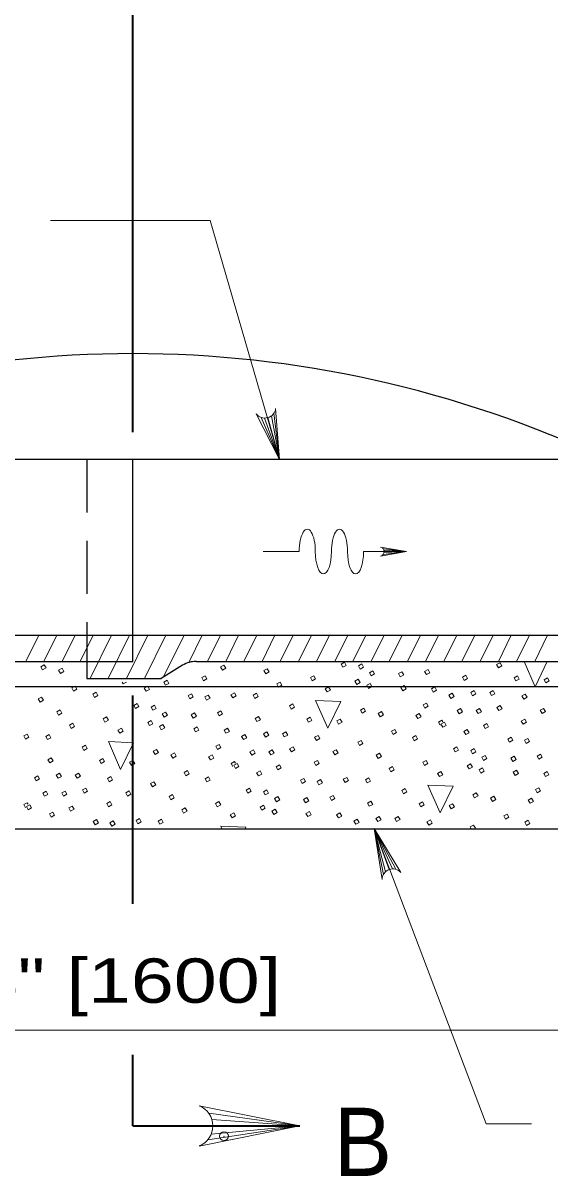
# Model space of a CAD drawing. Extents: x 1083.1 to 1117.1, y 697.4 to 741.4.
# Drawn here: x 1089.838 to 1091.69, y 728.285 to 732.34 of the extents above; entities that cross this region are included whole.
import ezdxf

# ---------------------------------------------------------------- set-up
doc = ezdxf.new("R2010")
doc.units = 0
doc.header["$LTSCALE"] = 0.062
doc.header["$PDMODE"] = 32
doc.header["$PDSIZE"] = 0.031
doc.linetypes.add('MEDIUM_DASHED', pattern=[4.5, 3, -1.5])
doc.layers.add('1', color=7, linetype='Continuous', lineweight=13)

msp = doc.modelspace()

# ---------------------------------------------------------------- linework, layer by layer
at = {"layer": '1', "lineweight": 35}
for p, q in [((1090.224, 730.90125), (1090.224, 736.59083)), ((1090.224, 729.24258), (1090.224, 729.975)), ((1090.224, 728.46133), (1090.224, 728.71075)), ((1090.224, 728.46133), (1090.81125, 728.46133))]:
    msp.add_line(p, q, dxfattribs=at)
at = {"layer": '1'}
for p, q in [((1089.93483, 731.64508), (1090.49583, 731.64508)), ((1090.74, 730.80458), (1090.49583, 731.64508)), ((1090.67483, 730.95267), (1090.74, 730.80458)), ((1090.687, 730.9505), (1090.74, 730.80458)), ((1090.69833, 730.952), (1090.74, 730.80458)), ((1090.71142, 730.95867), (1090.74, 730.80458)), ((1090.71975, 730.96733), (1090.74, 730.80458)), ((1091.18533, 730.481), (1091.09475, 730.497)), ((1091.18533, 730.481), (1091.10467, 730.49067)), ((1091.18533, 730.481), (1091.10483, 730.49067)), ((1091.18533, 730.481), (1091.10708, 730.48533)), ((1090.80883, 730.481), (1090.68258, 730.481)), ((1091.18533, 730.481), (1091.035, 730.481)), ((1091.18533, 730.481), (1091.09475, 730.465)), ((1091.18533, 730.481), (1091.10442, 730.471)), ((1091.10725, 730.47717), (1091.18383, 730.48075)), ((1089.84767, 730.09458), (1089.893, 730.18667)), ((1089.9115, 730.09458), (1089.95692, 730.18667)), ((1089.97542, 730.09458), (1090.02083, 730.18667)), ((1090.03933, 730.09458), (1090.08467, 730.18667)), ((1090.07458, 730.0365), (1090.14858, 730.18667)), ((1090.13842, 730.0365), (1090.2125, 730.18667)), ((1090.20233, 730.0365), (1090.27633, 730.18667)), ((1090.224, 730.09458), (1090.224, 730.18667)), ((1090.26617, 730.0365), (1090.34025, 730.18667)), ((1090.33317, 730.04267), (1090.40408, 730.18667)), ((1090.42083, 730.09092), (1090.468, 730.18667)), ((1090.4865, 730.09458), (1090.53192, 730.18667)), ((1090.55033, 730.09458), (1090.59575, 730.18667)), ((1090.61425, 730.09458), (1090.65967, 730.18667)), ((1090.67817, 730.09458), (1090.7235, 730.18667)), ((1090.742, 730.09458), (1090.78742, 730.18667)), ((1090.80592, 730.09458), (1090.85133, 730.18667)), ((1090.86983, 730.09458), (1090.91517, 730.18667)), ((1090.93367, 730.09458), (1090.97908, 730.18667)), ((1090.99758, 730.09458), (1091.043, 730.18667)), ((1091.06142, 730.09458), (1091.10683, 730.18667)), ((1091.12533, 730.09458), (1091.17075, 730.18667)), ((1091.18925, 730.09458), (1091.23458, 730.18667)), ((1091.25308, 730.09458), (1091.2985, 730.18667)), ((1091.317, 730.09458), (1091.36242, 730.18667)), ((1091.38083, 730.09458), (1091.42625, 730.18667)), ((1091.44475, 730.09458), (1091.49017, 730.18667)), ((1091.50867, 730.09458), (1091.55408, 730.18667)), ((1091.5725, 730.09458), (1091.61792, 730.18667)), ((1091.63642, 730.09458), (1091.68183, 730.18667)), ((1091.30408, 729.8705), (1091.298, 729.88133)), ((1090.57558, 729.72533), (1090.5695, 729.73617)), ((1089.84708, 729.58025), (1089.841, 729.59108)), ((1090.53283, 729.515), (1090.53692, 729.50575)), ((1091.4135, 729.50575), (1091.40967, 729.51258)), ((1091.12492, 729.36275), (1091.07275, 729.50675)), ((1091.11233, 729.35525), (1091.07275, 729.50675)), ((1091.10467, 729.34592), (1091.07275, 729.50675)), ((1091.13617, 729.36508), (1091.07275, 729.50675)), ((1091.14842, 729.36375), (1091.07275, 729.50675)), ((1091.07275, 729.50675), (1091.46567, 728.469)), ((1087.74667, 728.79775), (1090.62692, 728.79775)), ((1090.62692, 728.79775), (1091.5165, 728.79775)), ((1091.5165, 728.79775), (1092.70133, 728.79775)), ((1090.49083, 728.50625), (1090.81125, 728.46133)), ((1090.487, 728.41183), (1090.81125, 728.46133)), ((1090.49933, 728.43258), (1090.81125, 728.46133)), ((1090.50167, 728.484), (1090.81125, 728.46133)), ((1090.505, 728.46133), (1090.81125, 728.46133)), ((1090.81125, 728.46133), (1090.57908, 728.46133)), ((1091.46567, 728.469), (1091.625, 728.469))]:
    msp.add_line(p, q, dxfattribs=at)
at = {"layer": '1', "lineweight": 25}
for p, q in [((1092.05342, 730.80458), (1088.33592, 730.80458)), ((1090.224, 730.09458), (1090.224, 730.80458)), ((1088.33592, 730.18667), (1093.23292, 730.18667)), ((1088.55792, 730.09458), (1090.224, 730.09458)), ((1090.39883, 730.08117), (1090.323, 730.03458)), ((1090.446, 730.09458), (1092.05342, 730.09458)), ((1087.74667, 730.00642), (1092.69942, 730.00642)), ((1087.74667, 729.50575), (1092.70133, 729.50575))]:
    msp.add_line(p, q, dxfattribs=at)
at = {"layer": '1', "linetype": 'MEDIUM_DASHED', "lineweight": 25}
msp.add_line((1090.06217, 730.80458), (1090.06217, 730.09233), dxfattribs=at)
at = {"layer": '1'}
for points in [[(1090.72592, 730.98458), (1090.74, 730.80458), (1090.65775, 730.96533)], [(1091.59883, 730.09383), (1091.6375, 730.00533), (1091.68058, 730.09408)], [(1090.20158, 730.02217), (1090.19008, 730.01567), (1090.18675, 730.02158)], [(1091.298, 729.88133), (1091.30983, 729.88808), (1091.31308, 729.88242)], [(1090.5695, 729.73617), (1090.58133, 729.74292), (1090.58458, 729.73725)], [(1089.841, 729.59108), (1089.85283, 729.59783), (1089.85608, 729.59217)], [(1090.61825, 729.50575), (1090.621, 729.51125), (1090.53283, 729.515)], [(1091.40967, 729.51258), (1091.4215, 729.51933), (1091.42783, 729.50808), (1091.42367, 729.50575)], [(1091.09975, 729.32833), (1091.07275, 729.50675), (1091.16633, 729.35242)], [(1090.45725, 728.39058), (1090.81125, 728.46133), (1090.45725, 728.53217)]]:
    msp.add_lwpolyline(points, dxfattribs=at)
for points in [[(1089.90067, 730.07617), (1089.9125, 730.08283), (1089.91883, 730.07167), (1089.907, 730.06492)], [(1090.5325, 730.07525), (1090.54433, 730.08192), (1090.55067, 730.07067), (1090.53883, 730.064)], [(1090.95575, 730.08517), (1090.96758, 730.09192), (1090.97392, 730.08067), (1090.96208, 730.074)], [(1091.01675, 730.07908), (1091.02858, 730.08583), (1091.03492, 730.07458), (1091.02308, 730.06783)], [(1091.50258, 730.08342), (1091.5145, 730.09008), (1091.52083, 730.07892), (1091.509, 730.07217)], [(1089.96317, 730.06367), (1089.975, 730.07042), (1089.98133, 730.05917), (1089.9695, 730.05242)], [(1090.46592, 730.03758), (1090.47775, 730.04425), (1090.48408, 730.033), (1090.47225, 730.02633)], [(1090.68475, 730.06242), (1090.69658, 730.06917), (1090.703, 730.05792), (1090.69108, 730.05117)], [(1090.84817, 730.03767), (1090.86, 730.04442), (1090.86633, 730.03317), (1090.8545, 730.02642)], [(1091.05567, 730.05508), (1091.0675, 730.06175), (1091.07383, 730.0505), (1091.062, 730.04383)], [(1091.15775, 730.05175), (1091.16967, 730.0585), (1091.176, 730.04725), (1091.16408, 730.0405)], [(1091.24967, 730.05958), (1091.26158, 730.06625), (1091.26792, 730.055), (1091.25608, 730.04833)], [(1091.38242, 730.03925), (1091.39425, 730.046), (1091.40058, 730.03475), (1091.38875, 730.028)], [(1091.56375, 730.037), (1091.57558, 730.04375), (1091.58192, 730.0325), (1091.57008, 730.02583)], [(1090.00925, 730.00142), (1090.02108, 730.00817), (1090.02742, 729.99692), (1090.01558, 729.99017)], [(1090.26425, 730.00092), (1090.27608, 730.00758), (1090.28242, 729.99633), (1090.27058, 729.98967)], [(1090.33258, 730.02208), (1090.34442, 730.02883), (1090.35075, 730.01758), (1090.33892, 730.01083)], [(1090.72975, 730.0155), (1090.74158, 730.02225), (1090.74792, 730.011), (1090.73608, 730.00433)], [(1090.90017, 729.9985), (1090.912, 730.00517), (1090.91842, 729.99392), (1090.9065, 729.98725)], [(1091.00458, 730.02525), (1091.01642, 730.032), (1091.02275, 730.02075), (1091.01092, 730.014)], [(1091.04625, 730.01075), (1091.05808, 730.01742), (1091.06442, 730.00625), (1091.05258, 729.9995)], [(1091.16617, 730.00283), (1091.178, 730.00958), (1091.18442, 729.99833), (1091.1725, 729.99158)], [(1091.2735, 729.99825), (1091.28533, 730.005), (1091.29167, 729.99375), (1091.27983, 729.987)], [(1091.6695, 730.03033), (1091.68133, 730.03708), (1091.68767, 730.02583), (1091.67583, 730.01908)], [(1089.89133, 729.96258), (1089.90317, 729.96933), (1089.9095, 729.95808), (1089.89767, 729.95133)], [(1090.08308, 729.97942), (1090.09492, 729.98617), (1090.10125, 729.97492), (1090.08942, 729.96825)], [(1090.41825, 729.97433), (1090.43008, 729.981), (1090.43642, 729.96975), (1090.42458, 729.96308)], [(1090.477, 729.96992), (1090.48883, 729.97658), (1090.49517, 729.96533), (1090.48333, 729.95867)], [(1090.56892, 729.97767), (1090.58075, 729.98442), (1090.58708, 729.97317), (1090.57525, 729.96642)], [(1090.64642, 729.976), (1090.65825, 729.98275), (1090.66458, 729.9715), (1090.65275, 729.96475)], [(1090.86642, 729.95767), (1090.909, 729.86025), (1090.95458, 729.95392)], [(1091.33475, 729.976), (1091.34658, 729.98275), (1091.35292, 729.9715), (1091.34108, 729.96475)], [(1091.41183, 729.98517), (1091.42367, 729.99192), (1091.43, 729.98067), (1091.41817, 729.97392)], [(1091.4785, 729.9855), (1091.49033, 729.99225), (1091.49667, 729.981), (1091.48483, 729.97425)], [(1091.59142, 729.97308), (1091.60333, 729.97983), (1091.60967, 729.96858), (1091.59775, 729.96183)], [(1089.95625, 729.91733), (1089.96817, 729.924), (1089.9745, 729.91283), (1089.96258, 729.90608)], [(1090.22725, 729.94008), (1090.23908, 729.94683), (1090.24542, 729.93558), (1090.23358, 729.92883)], [(1090.28825, 729.934), (1090.30008, 729.94067), (1090.30642, 729.92942), (1090.29458, 729.92275)], [(1090.32717, 729.90992), (1090.339, 729.91667), (1090.34533, 729.90542), (1090.3335, 729.89867)], [(1090.52125, 729.91442), (1090.53308, 729.92117), (1090.53942, 729.90992), (1090.52758, 729.90317)], [(1090.77417, 729.93825), (1090.786, 729.945), (1090.79233, 729.93375), (1090.7805, 729.927)], [(1091.02408, 729.92367), (1091.03592, 729.93042), (1091.04225, 729.91917), (1091.03042, 729.91242)], [(1091.0865, 729.91125), (1091.09833, 729.918), (1091.10475, 729.90675), (1091.09283, 729.9)], [(1091.24408, 729.9415), (1091.25592, 729.94817), (1091.26225, 729.937), (1091.25042, 729.93025)], [(1091.36417, 729.92192), (1091.376, 729.92867), (1091.38233, 729.91742), (1091.3705, 729.91067)], [(1091.43083, 729.92225), (1091.44267, 729.929), (1091.449, 729.91775), (1091.43717, 729.911)], [(1091.50358, 729.93292), (1091.51542, 729.93958), (1091.52175, 729.92833), (1091.50992, 729.92167)], [(1091.65583, 729.92275), (1091.66767, 729.9295), (1091.674, 729.91825), (1091.66217, 729.9115)], [(1090.00125, 729.87042), (1090.01308, 729.87717), (1090.01942, 729.86592), (1090.00758, 729.85917)], [(1090.11967, 729.8925), (1090.1315, 729.89925), (1090.13783, 729.888), (1090.126, 729.88133)], [(1090.27608, 729.88017), (1090.28792, 729.88683), (1090.29425, 729.87558), (1090.28242, 729.86892)], [(1090.42925, 729.90667), (1090.44117, 729.91333), (1090.4475, 729.90208), (1090.43567, 729.89542)], [(1090.65392, 729.89417), (1090.66575, 729.90083), (1090.67208, 729.88958), (1090.66025, 729.88292)], [(1090.83525, 729.89192), (1090.84708, 729.89867), (1090.85342, 729.88742), (1090.84158, 729.88067)], [(1090.941, 729.88517), (1090.95283, 729.89192), (1090.95925, 729.88067), (1090.94733, 729.87392)], [(1091.21892, 729.90467), (1091.23075, 729.91133), (1091.23708, 729.90008), (1091.22525, 729.89342)], [(1091.30708, 729.8745), (1091.31892, 729.88117), (1091.32525, 729.86992), (1091.31342, 729.86325)], [(1091.45592, 729.86967), (1091.46775, 729.87633), (1091.47408, 729.86508), (1091.46225, 729.85842)], [(1091.58933, 729.88508), (1091.60117, 729.89183), (1091.6075, 729.88058), (1091.59567, 729.87383)], [(1089.84042, 729.83258), (1089.85225, 729.83933), (1089.85858, 729.82808), (1089.84675, 729.82133)], [(1089.91792, 729.83083), (1089.92975, 729.83758), (1089.93608, 729.82633), (1089.92425, 729.81958)], [(1090.17167, 729.85333), (1090.18358, 729.86008), (1090.18992, 729.84883), (1090.17808, 729.84208)], [(1090.31775, 729.86558), (1090.32958, 729.87233), (1090.33592, 729.86108), (1090.32408, 729.85433)], [(1090.43775, 729.85775), (1090.44958, 729.86442), (1090.45592, 729.85325), (1090.44408, 729.8465)], [(1090.545, 729.85317), (1090.55683, 729.85983), (1090.56317, 729.84858), (1090.55133, 729.84192)], [(1090.60625, 729.83083), (1090.61808, 729.83758), (1090.62442, 729.82633), (1090.61258, 729.81967)], [(1090.68333, 729.84008), (1090.69517, 729.84675), (1090.7015, 729.8355), (1090.68967, 729.82883)], [(1090.75, 729.84042), (1090.76183, 729.84708), (1090.76817, 729.83583), (1090.75633, 729.82917)], [(1091.13267, 729.849), (1091.1445, 729.85567), (1091.15083, 729.84442), (1091.139, 729.83775)], [(1091.38758, 729.84842), (1091.39942, 729.85517), (1091.40575, 729.84392), (1091.39392, 729.83717)], [(1090.04567, 729.79317), (1090.0575, 729.79983), (1090.06383, 729.78867), (1090.052, 729.78192)], [(1090.13792, 729.81258), (1090.1805, 729.71508), (1090.22608, 729.80883)], [(1090.51558, 729.79633), (1090.52742, 729.80308), (1090.53375, 729.79183), (1090.52192, 729.78508)], [(1090.77508, 729.78775), (1090.78692, 729.7945), (1090.79333, 729.78325), (1090.78142, 729.7765)], [(1090.86292, 729.82792), (1090.87483, 729.83467), (1090.88117, 729.82342), (1090.86933, 729.81675)], [(1091.01475, 729.81017), (1091.02658, 729.81692), (1091.03292, 729.80567), (1091.02108, 729.79892)], [(1091.2065, 729.827), (1091.21833, 729.83375), (1091.22467, 729.8225), (1091.21283, 729.81575)], [(1091.35067, 729.78767), (1091.3625, 729.79433), (1091.36883, 729.78308), (1091.357, 729.77642)], [(1091.54167, 729.82183), (1091.5535, 729.82858), (1091.55983, 729.81733), (1091.548, 729.81058)], [(1091.60033, 729.81742), (1091.61217, 729.82417), (1091.6185, 729.81292), (1091.60667, 729.80617)], [(1089.92542, 729.749), (1089.93725, 729.75575), (1089.94358, 729.7445), (1089.93175, 729.73775)], [(1090.29558, 729.77858), (1090.30742, 729.78525), (1090.31375, 729.77408), (1090.30192, 729.76733)], [(1090.358, 729.76608), (1090.36992, 729.77283), (1090.37625, 729.76158), (1090.36433, 729.75492)], [(1090.49042, 729.7595), (1090.50225, 729.76625), (1090.50858, 729.755), (1090.49675, 729.74825)], [(1090.63567, 729.77675), (1090.6475, 729.7835), (1090.65383, 729.77225), (1090.642, 729.76558)], [(1090.70233, 729.77708), (1090.71417, 729.78383), (1090.7205, 729.77258), (1090.70867, 729.76592)], [(1090.92733, 729.77767), (1090.93917, 729.78433), (1090.9455, 729.77317), (1090.93367, 729.76642)], [(1091.07967, 729.76483), (1091.0915, 729.77158), (1091.09783, 729.76033), (1091.086, 729.75367)], [(1091.41167, 729.7815), (1091.4235, 729.78825), (1091.42983, 729.777), (1091.418, 729.77025)], [(1091.45058, 729.7575), (1091.46242, 729.76417), (1091.46875, 729.753), (1091.45692, 729.74625)], [(1091.55267, 729.75417), (1091.5645, 729.76092), (1091.57083, 729.74967), (1091.559, 729.74292)], [(1091.64458, 729.762), (1091.65642, 729.76867), (1091.66275, 729.7575), (1091.65092, 729.75075)], [(1090.10675, 729.74683), (1090.11858, 729.7535), (1090.12492, 729.74225), (1090.11308, 729.73558)], [(1090.2125, 729.74008), (1090.22442, 729.74683), (1090.23075, 729.73558), (1090.21883, 729.72883)], [(1090.57858, 729.72933), (1090.59042, 729.73608), (1090.59683, 729.72483), (1090.58492, 729.71808)], [(1090.72742, 729.7245), (1090.73925, 729.73125), (1090.74558, 729.72), (1090.73375, 729.71325)], [(1090.86083, 729.74), (1090.87267, 729.74667), (1090.879, 729.7355), (1090.86717, 729.72875)], [(1091.12467, 729.718), (1091.1365, 729.72467), (1091.14283, 729.71342), (1091.131, 729.70675)], [(1091.24308, 729.74008), (1091.25492, 729.74683), (1091.26125, 729.73558), (1091.24942, 729.72883)], [(1091.39942, 729.72767), (1091.41133, 729.73442), (1091.41767, 729.72317), (1091.40575, 729.71642)], [(1091.44117, 729.71317), (1091.453, 729.71992), (1091.45933, 729.70867), (1091.4475, 729.70192)], [(1089.87775, 729.68575), (1089.88958, 729.6925), (1089.89592, 729.68125), (1089.88408, 729.6745)], [(1089.95483, 729.69492), (1089.96667, 729.70167), (1089.973, 729.69042), (1089.96117, 729.68367)], [(1090.0215, 729.69525), (1090.03333, 729.702), (1090.03967, 729.69075), (1090.02783, 729.684)], [(1090.1345, 729.68283), (1090.14633, 729.68958), (1090.15267, 729.67833), (1090.14083, 729.67158)], [(1090.40417, 729.70383), (1090.416, 729.71058), (1090.42233, 729.69933), (1090.4105, 729.69258)], [(1090.478, 729.68192), (1090.48983, 729.68858), (1090.49617, 729.67733), (1090.48433, 729.67067)], [(1090.65908, 729.70333), (1090.67092, 729.71), (1090.67733, 729.69875), (1090.66542, 729.69208)], [(1090.81317, 729.67675), (1090.825, 729.68342), (1090.83133, 729.67217), (1090.8195, 729.6655)], [(1090.87183, 729.67233), (1090.88367, 729.679), (1090.89, 729.66775), (1090.87817, 729.66108)], [(1090.96375, 729.68008), (1090.97558, 729.68683), (1090.98192, 729.67558), (1090.97008, 729.66892)], [(1091.04133, 729.67842), (1091.05317, 729.68517), (1091.0595, 729.67392), (1091.04767, 729.66717)], [(1091.29508, 729.70092), (1091.30692, 729.70758), (1091.31325, 729.69633), (1091.30142, 729.68967)], [(1091.56108, 729.70525), (1091.57292, 729.712), (1091.57925, 729.70075), (1091.56742, 729.69408)], [(1091.66842, 729.70067), (1091.68025, 729.70742), (1091.68658, 729.69617), (1091.67475, 729.68942)], [(1089.90717, 729.63167), (1089.919, 729.63842), (1089.92533, 729.62717), (1089.9135, 729.62042)], [(1089.97383, 729.632), (1089.98567, 729.63875), (1089.992, 729.6275), (1089.98017, 729.62075)], [(1090.04658, 729.64267), (1090.0585, 729.64933), (1090.06483, 729.63808), (1090.05292, 729.63142)], [(1090.19883, 729.6325), (1090.21067, 729.63925), (1090.21708, 729.628), (1090.20517, 729.62125)], [(1090.28625, 729.665), (1090.29808, 729.67175), (1090.30442, 729.6605), (1090.29258, 729.65383)], [(1090.62217, 729.6425), (1090.634, 729.64925), (1090.64033, 729.638), (1090.6285, 729.63125)], [(1090.68317, 729.63642), (1090.695, 729.64308), (1090.70133, 729.63183), (1090.6895, 729.62517)], [(1091.169, 729.64067), (1091.18083, 729.64742), (1091.18717, 729.63617), (1091.17533, 729.6295)], [(1091.26133, 729.66008), (1091.30383, 729.56267), (1091.3495, 729.65642)], [(1091.41892, 729.62608), (1091.43083, 729.63283), (1091.43717, 729.62158), (1091.42525, 729.61492)], [(1091.63892, 729.64392), (1091.65075, 729.65067), (1091.65717, 729.63942), (1091.64525, 729.63267)], [(1090.13233, 729.59483), (1090.14417, 729.60158), (1090.1505, 729.59033), (1090.13867, 729.58358)], [(1090.35117, 729.61975), (1090.363, 729.6265), (1090.36933, 729.61525), (1090.3575, 729.6085)], [(1090.51458, 729.595), (1090.52642, 729.60167), (1090.53275, 729.59042), (1090.52092, 729.58375)], [(1090.72208, 729.61233), (1090.73392, 729.61908), (1090.74025, 729.60783), (1090.72842, 729.60108)], [(1090.82417, 729.60908), (1090.836, 729.61575), (1090.84233, 729.6045), (1090.8305, 729.59783)], [(1090.91608, 729.61683), (1090.92792, 729.62358), (1090.93425, 729.61233), (1090.92242, 729.60558)], [(1091.04875, 729.59658), (1091.06067, 729.60325), (1091.067, 729.592), (1091.05508, 729.58533)], [(1091.23017, 729.59433), (1091.242, 729.60108), (1091.24833, 729.58983), (1091.2365, 729.58308)], [(1091.33592, 729.58767), (1091.34775, 729.59433), (1091.35408, 729.58308), (1091.34225, 729.57642)], [(1091.48142, 729.61367), (1091.49325, 729.62042), (1091.49958, 729.60917), (1091.48775, 729.60242)], [(1091.61375, 729.60708), (1091.62567, 729.61375), (1091.632, 729.60258), (1091.62017, 729.59583)], [(1089.85008, 729.58425), (1089.862, 729.59092), (1089.86833, 729.57967), (1089.85642, 729.573)], [(1089.93058, 729.55817), (1089.9425, 729.56492), (1089.94883, 729.55367), (1089.93692, 729.54692)], [(1089.99892, 729.57942), (1090.01075, 729.58608), (1090.01717, 729.57483), (1090.00525, 729.56817)], [(1090.39617, 729.57283), (1090.408, 729.57958), (1090.41433, 729.56833), (1090.4025, 729.56158)], [(1090.56658, 729.55575), (1090.57842, 729.5625), (1090.58475, 729.55125), (1090.57292, 729.5445)], [(1090.671, 729.58258), (1090.68283, 729.58933), (1090.68917, 729.57808), (1090.67733, 729.57133)], [(1090.71267, 729.568), (1090.7245, 729.57475), (1090.73083, 729.5635), (1090.719, 729.55683)], [(1090.83258, 729.56017), (1090.84442, 729.56692), (1090.85075, 729.55567), (1090.83892, 729.54892)], [(1090.93992, 729.55558), (1090.95175, 729.56225), (1090.95808, 729.551), (1090.94625, 729.54433)], [(1091.5275, 729.55142), (1091.53933, 729.55808), (1091.54567, 729.54692), (1091.53383, 729.54017)], [(1090.08467, 729.53158), (1090.0965, 729.53833), (1090.10283, 729.52708), (1090.091, 729.52033)], [(1090.14333, 729.52717), (1090.15517, 729.53392), (1090.16158, 729.52267), (1090.14967, 729.51592)], [(1090.23525, 729.535), (1090.24717, 729.54175), (1090.2535, 729.5305), (1090.24158, 729.52375)], [(1090.31283, 729.53325), (1090.32467, 729.54), (1090.331, 729.52875), (1090.31917, 729.52208)], [(1091.00108, 729.53333), (1091.013, 729.54), (1091.01933, 729.52875), (1091.00742, 729.52208)], [(1091.07825, 729.5425), (1091.09008, 729.54917), (1091.09642, 729.53792), (1091.08458, 729.53125)], [(1091.14492, 729.54283), (1091.15675, 729.5495), (1091.16308, 729.53825), (1091.15125, 729.53158)], [(1091.25783, 729.53042), (1091.26967, 729.53708), (1091.276, 729.52583), (1091.26417, 729.51917)], [(1091.60142, 729.52942), (1091.61325, 729.53617), (1091.61958, 729.52492), (1091.60775, 729.51817)]]:
    msp.add_lwpolyline(points, close=True, dxfattribs=at)
at = {"layer": '1', "lineweight": 25}
msp.add_lwpolyline([(1090.06217, 730.09233), (1090.06217, 730.03458), (1090.323, 730.03458)], dxfattribs=at)
at = {"layer": '1'}
for centre, radius, start, end in [((1090.68792, 730.98867), 0.0382, 217.86798, 353.69411), ((1091.13795, 729.32693), 0.0382, 41.99928, 177.82541), ((1090.4287, 728.46145), 0.0764, 292.08605, 67.91218)]:
    msp.add_arc(centre, radius, start, end, dxfattribs=at)
at = {"layer": '1', "lineweight": 25}
for centre, major_axis, start_param, end_param in [((1090.22398, 726.80542), (0, 4.37154), 5.8674479, 6.6989234), ((1090.44602, 729.99463), (0, 0.09994), 0.0000001, 0.5236033)]:
    msp.add_ellipse(centre, major_axis=major_axis, ratio=0.944544, start_param=start_param, end_param=end_param, dxfattribs=at)
at = {"layer": '1'}
for centre, major_axis, ratio, start_param, end_param in [((1090.83711, 730.48102), (0, -0.07867), 0.359358, 1.5707963, 4.712389), ((1090.9502, 730.48102), (0, -0.07867), 0.359358, 1.5707963, 4.712389), ((1091.09239, 730.48102), (0, -0.01618), 0.944544, 0.1533668, 2.9873365), ((1090.89365, 730.48102), (0, -0.07867), 0.359358, 4.712389, 7.8539816), ((1091.00674, 730.48102), (0, -0.07867), 0.359358, 4.712389, 7.8539816)]:
    msp.add_ellipse(centre, major_axis=major_axis, ratio=ratio, start_param=start_param, end_param=end_param, dxfattribs=at)
msp.add_point((1090.54433, 728.42517), dxfattribs=at)

# ---------------------------------------------------------------- texts
for s, height, width, p in [('5\'-4" [1600]', 0.156, 1.3, (1089.37567, 728.89417)), ('B', 0.24, 0.95, (1090.93108, 728.28533))]:
    msp.add_text(s, height=height, dxfattribs=dict(at, width=width)).set_placement(p)

doc.saveas('drawing.dxf')
